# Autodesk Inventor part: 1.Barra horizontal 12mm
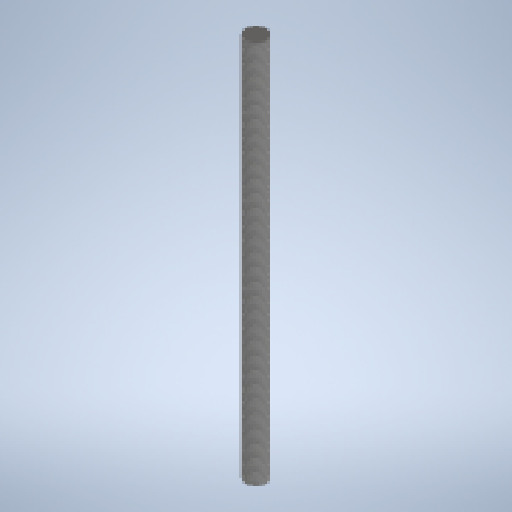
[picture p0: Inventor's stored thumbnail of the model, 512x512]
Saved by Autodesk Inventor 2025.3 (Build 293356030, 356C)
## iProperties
Created: 2025-10
Part Number: 1.Barra horizontal 12mm
Material: Genérico
Document SubType Name: Modeling
Designer: User
Density: 1 g/cm^3
Appearance: Valor por defecto
Author: User
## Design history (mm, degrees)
sketch "Boceto1"
  geometry: C1 r 6 at (0, 0); 1 further point
  constraints: 1 centre point
  dimensions: "d0" = 0 distance of point (0, 0) C1.centre; "d1" = 0 distance of C1.centre point (0, 0); "d2" = 12 diameter of C1
extrude "Extrusión1" new body sketch "Boceto1" stored distance "d3" = 220; taper "d4" = 0 deg
feature "Rosca1" dims "d5" = 200, "d6" = 0
node "Sólido1"
node "Acabados"
node "Finish1" dims "Finish1_Area" = 851.99993
